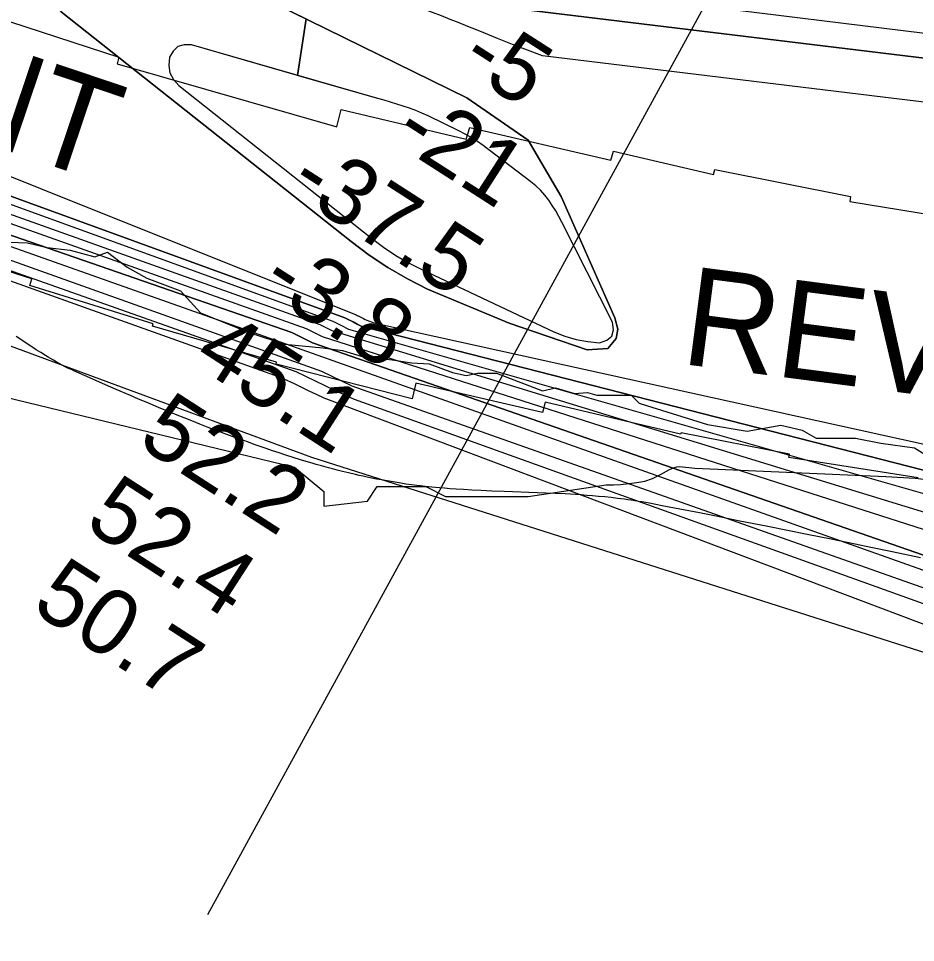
# Model space of a CAD drawing. Extents: x 3161615 to 3199515, y 867541 to 892976.
# Drawn here: x 3183730 to 3184643, y 877663 to 878603 of the extents above; entities that cross this region are included whole.
import ezdxf

# ---------------------------------------------------------------- set-up
doc = ezdxf.new("R2010")
doc.units = 0
for name, color, linetype in [('V-RIVR-EDGE', 7, 'Continuous'), ('V-RIVR-RANG', 7, 'Continuous'), ('V-ROAD-CNTR', 7, 'Continuous'), ('V-RRAP-RVMT', 7, 'Continuous'), ('V-RRAP-RVMT-IDEN', 7, 'Continuous'), ('V-SITE-VEGE', 7, 'Continuous'), ('V-TOPO-DPTH', 7, 'Continuous'), ('V-TOPO-MAJR', 7, 'Continuous'), ('V-TOPO-MINR', 7, 'Continuous'), ('V-TOPO-WATR', 7, 'Continuous')]:
    doc.layers.add(name, color=color, linetype=linetype)

msp = doc.modelspace()

# ---------------------------------------------------------------- linework, layer by layer
at = {"layer": 'V-RIVR-EDGE'}
msp.add_lwpolyline([(3183720.689197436, 878375.4628271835), (3183739.2860465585, 878374.9399670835), (3183759.3029007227, 878370.1217167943), (3183782.6625792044, 878367.2027024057), (3183807.9203144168, 878360.4639911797), (3183820.8076641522, 878365.2008788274), (3183840.798576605, 878349.8914330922), (3183860.8001015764, 878338.8738400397), (3183895.1030854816, 878325.9133818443), (3183915.5531829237, 878303.4496691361), (3183965.5752724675, 878283.2972105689), (3184001.312411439, 878271.7638324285), (3184039.929652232, 878267.8533396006), (3184059.9524022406, 878265.4194519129), (3184079.0131530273, 878259.649814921), (3184110.4773060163, 878255.7570096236), (3184130.4988768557, 878252.8462494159), (3184148.1408017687, 878251.8488751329), (3184171.962023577, 878242.7293388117), (3184185.784251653, 878239.8339077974), (3184197.2350879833, 878242.1899703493), (3184216.786861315, 878242.141624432), (3184263.47673906, 878224.3817826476), (3184276.8362446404, 878227.2100010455), (3184295.896995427, 878221.4403640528), (3184309.2517843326, 878222.3610923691), (3184318.783338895, 878219.9531463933), (3184338.335112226, 878219.904800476), (3184353.595032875, 878219.8670670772), (3184361.681819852, 878211.7401883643), (3184369.305884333, 878209.3369590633), (3184431.252145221, 878190.1087663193), (3184471.7698010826, 878183.3323216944), (3184506.119951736, 878189.4467643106), (3184527.566244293, 878184.1481039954), (3184541.852374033, 878176.0058960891), (3184581.9096657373, 878175.906845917), (3184607.648990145, 878171.0744456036), (3184641.9720199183, 878166.2208202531), (3184652.9235795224, 878159.5174840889)], dxfattribs=at)
at = {"layer": 'V-RIVR-RANG'}
msp.add_line((3183922.7562000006, 877691.4420999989), (3184460.0887000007, 878674.129099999), dxfattribs=at)
at = {"layer": 'V-ROAD-CNTR'}
for points in [[(3183762.9754372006, 878256.957458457), (3183760.3264424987, 878258.5414552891), (3183757.771447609, 878260.0984521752), (3183752.850457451, 878263.1684460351), (3183748.263466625, 878266.0984401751), (3183743.978475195, 878268.877434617), (3183727.9335072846, 878279.3824136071)], [(3184353.793255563, 878112.8857466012), (3184350.248262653, 878113.4027455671), (3184346.755269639, 878113.8867445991), (3184343.313276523, 878114.341743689), (3184339.9232833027, 878114.768742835), (3184333.2412966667, 878115.5517412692), (3184326.759309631, 878116.2417398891), (3184320.4723222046, 878116.8487386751), (3184314.3743344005, 878117.3847376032), (3184308.4613462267, 878117.8577366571), (3184302.7283576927, 878118.2777358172), (3184297.169368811, 878118.6497350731), (3184291.7803795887, 878118.980734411), (3184286.556390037, 878119.276733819), (3184276.427410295, 878119.7897327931), (3184266.9224293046, 878120.210731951), (3184258.006447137, 878120.565731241), (3184224.542514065, 878121.764728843), (3184211.993539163, 878122.246727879), (3184201.018561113, 878122.724726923), (3184191.420580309, 878123.203725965), (3184183.0285970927, 878123.6817250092), (3184175.690611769, 878124.153724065), (3184169.2756245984, 878124.6127231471), (3184163.6656358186, 878125.0527222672), (3184158.760645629, 878125.4707214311), (3184154.471654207, 878125.8627206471), (3184150.721661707, 878126.2267199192), (3184144.163674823, 878126.9147185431), (3184139.2506846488, 878127.475717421), (3184135.567692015, 878127.922716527), (3184130.049703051, 878128.6377150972), (3184124.537714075, 878129.4097135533), (3184117.716727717, 878130.4387114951), (3184111.3387404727, 878131.468709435), (3184105.3717524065, 878132.4917073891), (3184099.7897635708, 878133.4997053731), (3184094.565774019, 878134.4887033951), (3184089.6757837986, 878135.4537014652), (3184085.0987929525, 878136.3906995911), (3184080.813801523, 878137.2986977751), (3184076.8008095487, 878138.174696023), (3184073.042817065, 878139.0176943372), (3184066.007831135, 878140.6546910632), (3184059.862843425, 878142.147688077), (3184054.4928541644, 878143.499685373), (3184049.8008635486, 878144.7176829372), (3184045.6988717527, 878145.8086807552), (3184038.5278860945, 878147.7776768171), (3184033.156896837, 878149.3026737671), (3184029.1319048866, 878150.4726714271), (3184023.099916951, 878152.271667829), (3184017.073929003, 878154.1216641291), (3184009.6319438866, 878156.463659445), (3184002.443958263, 878158.7746548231), (3183995.4999721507, 878161.0506502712), (3183988.789985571, 878163.2896457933), (3183982.305998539, 878165.490641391), (3183976.038011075, 878167.651637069), (3183969.9800231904, 878169.7706328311), (3183964.1230349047, 878171.848628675), (3183958.460046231, 878173.8826246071), (3183952.984057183, 878175.8746206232), (3183942.4010783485, 878179.7866127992), (3183932.5090981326, 878183.516605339), (3183923.2611166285, 878187.0665982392), (3183914.6121339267, 878190.4375914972), (3183906.5201501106, 878193.634585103), (3183898.949165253, 878196.6615790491), (3183891.862179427, 878199.5255733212), (3183885.229192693, 878202.2325679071), (3183872.8142175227, 878207.3595576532), (3183861.9742392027, 878211.897548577), (3183852.5042581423, 878215.9055405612), (3183844.2292746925, 878219.4375334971), (3183829.7673036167, 878225.6695210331), (3183818.9353252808, 878230.3825116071), (3183802.703357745, 878237.5024973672), (3183786.4843901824, 878244.6704830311), (3183784.694393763, 878245.475481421), (3183781.1994007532, 878247.1154781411), (3183777.8494074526, 878248.7674748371), (3183774.635413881, 878250.424471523), (3183771.548420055, 878252.0774682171), (3183768.5804259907, 878253.720464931), (3183765.7254317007, 878255.3494616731), (3183762.9754372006, 878256.957458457)], [(3184648.0726670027, 878054.4238635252), (3184619.2867245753, 878060.4308515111), (3184597.6857677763, 878064.8908425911), (3184581.479800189, 878068.2108359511), (3184557.160848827, 878073.1518260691), (3184532.8298974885, 878078.047816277), (3184492.719977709, 878086.0878001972), (3184462.639037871, 878092.100788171), (3184440.074083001, 878096.5817792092), (3184423.1461168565, 878099.917772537), (3184397.7451676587, 878104.871762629), (3184385.040193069, 878107.321757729), (3184372.330218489, 878109.750752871), (3184368.513226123, 878110.4597514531), (3184364.751233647, 878111.124750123), (3184361.044241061, 878111.7497488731), (3184357.3922483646, 878112.3357477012), (3184353.793255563, 878112.8857466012)]]:
    msp.add_lwpolyline(points, dxfattribs=at)
at = {"layer": 'V-RRAP-RVMT'}
for points in [[(3183706.105000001, 878604.868999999), (3183832.337000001, 878563.8749999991), (3183830.515000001, 878556.8459999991), (3184054.028000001, 878492.8359999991), (3184058.675000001, 878510.427999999), (3184185.892000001, 878480.216999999), (3184189.658000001, 878492.086999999), (3184332.954000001, 878459.067999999), (3184335.682000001, 878467.930999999), (3184437.409000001, 878444.4469999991), (3184438.708000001, 878449.4569999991), (3184576.690000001, 878421.8749999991), (3184575.9990000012, 878416.8799999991), (3184696.595000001, 878397.3649999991)], [(3184645.811000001, 878135.6279999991), (3184514.181000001, 878156.4659999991), (3184514.756000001, 878159.6799999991), (3184404.438000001, 878181.606999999), (3184403.980000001, 878180.1739999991), (3184266.022000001, 878212.837999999), (3184263.380000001, 878202.312999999), (3184134.399000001, 878232.0349999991), (3184130.778000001, 878216.072999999), (3183992.5190000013, 878251.2309999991), (3183992.944000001, 878253.5349999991), (3183866.490000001, 878290.015999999), (3183867.1780000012, 878292.337999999), (3183741.657000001, 878331.420999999), (3183743.901000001, 878338.0819999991), (3183618.972000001, 878377.787999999)]]:
    msp.add_lwpolyline(points, dxfattribs=at)
at = {"layer": 'V-SITE-VEGE'}
for points in [[(3183704.493000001, 878220.8049999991), (3184011.230000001, 878146.5569999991), (3184040.914000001, 878121.8069999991), (3184040.914000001, 878106.9569999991), (3184085.441000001, 878111.9069999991), (3184095.335000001, 878126.756999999), (3184144.809000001, 878126.756999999), (3184164.599000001, 878116.856999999), (3184248.704000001, 878116.856999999), (3184328.175000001, 878128.685999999)], [(3184328.175000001, 878128.685999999), (3184335.568000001, 878128.5329999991), (3184342.961000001, 878129.0759999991), (3184351.210000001, 878129.8929999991), (3184359.439000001, 878130.979999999), (3184367.543000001, 878132.466999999), (3184375.383000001, 878134.983999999), (3184383.520000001, 878139.0759999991), (3184392.641000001, 878144.131999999), (3184397.630000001, 878146.3089999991), (3184400.225000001, 878146.9809999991), (3184402.8570000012, 878147.2229999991), (3184418.594000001, 878145.3709999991), (3184612.906000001, 878137.1669999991), (3184642.557000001, 878135.3159999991), (3184657.345000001, 878133.8039999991)]]:
    msp.add_lwpolyline(points, dxfattribs=at)
at = {"layer": 'V-TOPO-DPTH'}
for points in [[(3183372.849847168, 878834.8355776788), (3184249.570273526, 878611.664489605), (3185230.8329057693, 878492.6025050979), (3185239.5889615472, 878489.9185044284), (3185248.3665675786, 878487.3086996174), (3185257.1764989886, 878484.8101885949), (3185266.0079806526, 878482.3858734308), (3186088.3919671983, 878334.1032975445), (3186116.9719442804, 878329.7201433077), (3186145.491880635, 878324.9143121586)], [(3184146.4127295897, 878327.8380489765), (3184126.0131929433, 878338.3115003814), (3184106.1699994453, 878349.6822995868), (3184087.16132067, 878362.3991204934), (3184068.7089850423, 878376.0132892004), (3183773.7889948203, 878609.8285210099), (3183764.761234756, 878619.8148607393), (3183758.256994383, 878630.7938620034), (3183755.5380335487, 878643.2618555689), (3183755.3425924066, 878656.7225106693), (3183760.127324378, 878667.3596378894), (3183766.8715389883, 878675.1564646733), (3183776.5549775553, 878678.692840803), (3183788.197898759, 878679.3889164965), (3183843.7690162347, 878667.4237620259), (3183855.273961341, 878664.8631988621), (3183865.506115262, 878709.428854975)], [(3183868.6918123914, 878708.617928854), (3183865.506115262, 878709.428854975), (3183855.273961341, 878664.8631988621), (3183857.6949213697, 878664.3243852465), (3183867.0813911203, 878662.235314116), (3183890.342454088, 878656.8326768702), (3183913.5265491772, 878651.10875562), (3183936.659332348, 878645.1706450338), (3184186.6065439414, 878522.222251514), (3184248.9785296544, 878479.1657162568), (3184282.446902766, 878422.1001908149), (3184336.879298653, 878298.6185323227), (3184339.9819446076, 878286.8990336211), (3184338.405226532, 878277.5302031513), (3184329.8022996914, 878267.3921345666), (3184308.724975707, 878265.8653730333), (3184229.600789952, 878293.2191795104), (3184146.4127295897, 878327.8380489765)], [(3186145.491880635, 878324.9143121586), (3186116.9719442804, 878329.7201433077), (3186088.3919671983, 878334.1032975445), (3185266.0079806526, 878482.3858734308), (3185257.1764989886, 878484.8101885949), (3185248.3665675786, 878487.3086996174), (3185239.5889615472, 878489.9185044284), (3185230.8329057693, 878492.6025050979), (3184249.570273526, 878611.664489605), (3183868.6918123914, 878708.617928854)], [(3184146.4127295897, 878327.8380489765), (3184126.0131929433, 878338.3115003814), (3184106.1699994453, 878349.6822995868), (3184087.16132067, 878362.3991204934), (3184068.7089850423, 878376.0132892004), (3183773.7889948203, 878609.8285210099), (3183764.761234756, 878619.8148607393), (3183758.256994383, 878630.7938620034), (3183755.5380335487, 878643.2618555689), (3183755.3425924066, 878656.7225106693), (3183760.127324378, 878667.3596378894), (3183766.8715389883, 878675.1564646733), (3183776.5549775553, 878678.692840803), (3183788.197898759, 878679.3889164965), (3183843.7690162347, 878667.4237620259), (3183867.0813911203, 878662.235314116), (3183890.342454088, 878656.8326768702), (3183913.5265491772, 878651.10875562), (3183936.659332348, 878645.1706450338), (3184022.9802118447, 878602.7096253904)], [(3184022.9802118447, 878602.7096253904), (3184014.048710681, 878545.2100843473), (3183906.153296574, 878576.1449049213), (3183898.760590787, 878576.266058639), (3183892.417922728, 878574.5265625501), (3183887.6503112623, 878569.9960917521), (3183883.9327375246, 878563.6049711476), (3183883.283302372, 878555.3971410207), (3183884.3624340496, 878547.7587348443), (3183888.034415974, 878540.9744645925), (3183893.434964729, 878534.7596182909), (3184089.337076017, 878379.4456817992), (3184101.5413851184, 878370.4413060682), (3184114.1136797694, 878362.0304750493), (3184127.237952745, 878354.5099610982), (3184140.73021127, 878347.5829918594), (3184275.0582020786, 878284.4066678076), (3184286.2552080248, 878279.9537376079), (3184297.6799251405, 878276.4416430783), (3184309.446209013, 878274.3408020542), (3184321.440204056, 878273.1807967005), (3184328.944188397, 878275.7332786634), (3184334.065478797, 878279.8084991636), (3184335.612728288, 878286.1678274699), (3184334.7772838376, 878294.0498943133), (3184283.240078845, 878395.8145595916), (3184280.1536255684, 878401.5939258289), (3184276.9047591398, 878407.2756835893)], [(3184276.9047591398, 878407.2756835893), (3184273.4122729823, 878412.8110286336), (3184269.757373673, 878418.2487652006), (3184265.7590821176, 878423.3994324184), (3184261.471871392, 878428.2709921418), (3184256.751281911, 878432.7238906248), (3184251.7417732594, 878436.8976816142), (3184203.067166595, 878473.7510171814), (3184197.1702966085, 878477.9456273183), (3184191.1240657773, 878481.8960863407), (3184184.853793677, 878485.4803186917), (3184178.4341607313, 878488.8203999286), (3184146.9625092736, 878504.022327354), (3184140.800349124, 878506.8333149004), (3184134.565205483, 878509.4598021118), (3184128.220586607, 878511.8095388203), (3184121.8029842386, 878513.9747751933), (3184115.3233377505, 878515.9774659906), (3184108.834277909, 878517.9487614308), (3184102.331098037, 878519.872963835), (3184095.818504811, 878521.7657708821), (3184021.084727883, 878543.1927796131), (3184014.048710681, 878545.2100843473), (3184022.9802118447, 878602.7096253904), (3184027.690381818, 878600.3927048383)], [(3183252.667433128, 878593.1972245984), (3184062.4632930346, 878298.5288033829), (3184066.549592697, 878296.3929994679), (3184070.641684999, 878294.2684087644), (3184074.742466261, 878292.160637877), (3184078.849040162, 878290.0640802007), (3184955.5760327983, 878065.4056483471)], [(3184955.5760327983, 878065.4056483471), (3184078.849040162, 878290.0640802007), (3184074.742466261, 878292.160637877), (3184070.641684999, 878294.2684087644), (3184066.549592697, 878296.3929994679), (3184062.4632930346, 878298.5288033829), (3183252.667433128, 878593.1972245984)], [(3184027.690381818, 878600.3927048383), (3184186.6065439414, 878522.222251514), (3184248.9785296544, 878479.1657162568), (3184282.446902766, 878422.1001908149), (3184336.879298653, 878298.6185323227), (3184339.9819446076, 878286.8990336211), (3184338.405226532, 878277.5302031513), (3184329.8022996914, 878267.3921345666), (3184308.724975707, 878265.8653730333), (3184229.600789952, 878293.2191795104), (3184146.4127295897, 878327.8380489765)], [(3183212.658256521, 878585.3971045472), (3184036.985233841, 878291.612818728), (3184049.0120516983, 878285.4660348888), (3184936.3581883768, 878013.7470163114)], [(3183212.658256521, 878585.3971045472), (3184036.985233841, 878291.612818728), (3184049.0120516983, 878285.4660348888), (3184936.3581883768, 878013.7470163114)], [(3184276.9047591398, 878407.2756835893), (3184273.4122729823, 878412.8110286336), (3184269.757373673, 878418.2487652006), (3184265.7590821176, 878423.3994324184), (3184261.471871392, 878428.2709921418), (3184256.751281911, 878432.7238906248), (3184251.7417732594, 878436.8976816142), (3184203.067166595, 878473.7510171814), (3184197.1702966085, 878477.9456273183), (3184191.1240657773, 878481.8960863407), (3184184.853793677, 878485.4803186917), (3184178.4341607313, 878488.8203999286), (3184146.9625092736, 878504.022327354), (3184140.800349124, 878506.8333149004), (3184134.565205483, 878509.4598021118), (3184128.220586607, 878511.8095388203), (3184121.8029842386, 878513.9747751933), (3184115.3233377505, 878515.9774659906), (3184108.834277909, 878517.9487614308), (3184102.331098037, 878519.872963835), (3184095.818504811, 878521.7657708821), (3183906.153296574, 878576.1449049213), (3183898.760590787, 878576.266058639), (3183892.417922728, 878574.5265625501), (3183887.6503112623, 878569.9960917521), (3183883.9327375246, 878563.6049711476), (3183883.283302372, 878555.3971410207), (3183884.3624340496, 878547.7587348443), (3183888.034415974, 878540.9744645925), (3183893.434964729, 878534.7596182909), (3184089.337076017, 878379.4456817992), (3184101.5413851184, 878370.4413060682), (3184114.1136797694, 878362.0304750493), (3184127.237952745, 878354.5099610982), (3184140.73021127, 878347.5829918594), (3184275.0582020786, 878284.4066678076), (3184286.2552080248, 878279.9537376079), (3184297.6799251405, 878276.4416430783), (3184309.446209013, 878274.3408020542), (3184321.440204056, 878273.1807967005), (3184328.944188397, 878275.7332786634), (3184334.065478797, 878279.8084991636), (3184335.612728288, 878286.1678274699), (3184334.7772838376, 878294.0498943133), (3184283.240078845, 878395.8145595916), (3184280.1536255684, 878401.5939258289), (3184276.9047591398, 878407.2756835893)], [(3184953.757013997, 877951.6936236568), (3184029.256940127, 878273.0675252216), (3184008.2494205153, 878283.5851602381), (3183219.0654344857, 878556.6295615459)]]:
    msp.add_lwpolyline(points, dxfattribs=at)
at = {"layer": 'V-TOPO-MAJR'}
msp.add_lwpolyline([(3183235.315423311, 878518.6069014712), (3184012.537934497, 878243.9726394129), (3184032.2175095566, 878234.4599938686), (3184051.9365608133, 878225.0294521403), (3184071.681929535, 878215.6536462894), (3184922.869589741, 877909.9897771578)], dxfattribs=at)
at = {"layer": 'V-TOPO-MINR'}
for points in [[(3186147.2983375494, 878379.3295241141), (3186128.676513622, 878384.1360410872), (3185314.401796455, 878506.3831856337), (3184277.182839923, 878634.3805067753), (3183394.0893720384, 878877.4493847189)], [(3186145.491880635, 878324.9143121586), (3186116.9719442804, 878329.7201433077), (3186088.3919671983, 878334.1032975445), (3185266.0079806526, 878482.3858734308), (3185257.1764989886, 878484.8101885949), (3185248.3665675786, 878487.3086996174), (3185239.5889615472, 878489.9185044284), (3185230.8329057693, 878492.6025050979), (3184249.570273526, 878611.664489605), (3183372.849847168, 878834.8355776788)], [(3184248.048062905, 878570.7617867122), (3184232.838272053, 878576.6644537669), (3184217.6935068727, 878582.7389662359), (3184205.327160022, 878587.8207488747), (3184196.407203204, 878591.4655654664), (3184187.477691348, 878595.0866845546), (3184178.5338469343, 878598.6722573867), (3184169.580447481, 878602.2341327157), (3184160.6010079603, 878605.7277883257), (3184151.596411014, 878609.1542021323), (3184142.554077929, 878612.479753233), (3184133.4865874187, 878615.7380625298), (3183388.1043961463, 878797.7976993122)], [(3183773.7889948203, 878609.8285210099), (3184068.7089850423, 878376.0132892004), (3184087.16132067, 878362.3991204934), (3184106.1699994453, 878349.6822995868), (3184126.0131929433, 878338.3115003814), (3184146.4127295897, 878327.8380489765), (3184229.600789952, 878293.2191795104), (3184308.724975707, 878265.8653730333), (3184329.8022996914, 878267.3921345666), (3184338.405226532, 878277.5302031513), (3184339.9819446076, 878286.8990336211), (3184336.879298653, 878298.6185323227), (3184282.446902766, 878422.1001908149), (3184248.9785296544, 878479.1657162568), (3184186.6065439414, 878522.222251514), (3183936.659332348, 878645.1706450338)], [(3183209.3966609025, 878599.9613887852), (3184050.155685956, 878295.2155285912), (3184058.074725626, 878291.123516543), (3184066.0049089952, 878287.0533270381), (3184958.843468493, 878031.8409783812)], [(3183252.667433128, 878593.1972245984), (3184062.4632930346, 878298.5288033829), (3184066.549592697, 878296.3929994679), (3184070.641684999, 878294.2684087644), (3184074.742466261, 878292.160637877), (3184078.849040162, 878290.0640802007), (3184955.5760327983, 878065.4056483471)], [(3183199.1219689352, 878580.4398783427), (3184022.996397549, 878287.731168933), (3184039.3922816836, 878279.4390277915), (3185015.7129105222, 877966.5873512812), (3185136.9727150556, 877934.1829453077), (3185214.0046340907, 877913.3547107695), (3185290.952817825, 877892.225011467), (3185367.7753986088, 877870.6431150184), (3185444.5142440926, 877848.7597538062), (3185700.183264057, 877775.037785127), (3185717.778624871, 877769.9374630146), (3185735.364350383, 877764.8043023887), (3185752.9356229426, 877759.6218839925), (3185770.4972602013, 877754.4066270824), (3185784.5371316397, 877750.2158097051), (3185795.1173655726, 877747.2675874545), (3185805.758422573, 877744.5802286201), (3185816.490714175, 877742.2841649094), (3185827.2838288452, 877740.2489646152), (3185838.144642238, 877738.6197384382), (3185849.034609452, 877737.2691896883), (3185859.9683073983, 877736.3366570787), (3185870.931159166, 877735.6828018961), (3186703.9569149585, 877684.4115282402)], [(3184276.9047591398, 878407.2756835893), (3184273.4122729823, 878412.8110286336), (3184269.757373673, 878418.2487652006), (3184265.7590821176, 878423.3994324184), (3184261.471871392, 878428.2709921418), (3184256.751281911, 878432.7238906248), (3184251.7417732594, 878436.8976816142), (3184203.067166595, 878473.7510171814), (3184197.1702966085, 878477.9456273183), (3184191.1240657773, 878481.8960863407), (3184184.853793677, 878485.4803186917), (3184178.4341607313, 878488.8203999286), (3184146.9625092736, 878504.022327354), (3184140.800349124, 878506.8333149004), (3184134.565205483, 878509.4598021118), (3184128.220586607, 878511.8095388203), (3184121.8029842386, 878513.9747751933), (3184115.3233377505, 878515.9774659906), (3184108.834277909, 878517.9487614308), (3184102.331098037, 878519.872963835), (3184095.818504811, 878521.7657708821), (3183906.153296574, 878576.1449049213), (3183898.760590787, 878576.266058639), (3183892.417922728, 878574.5265625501), (3183887.6503112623, 878569.9960917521), (3183883.9327375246, 878563.6049711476), (3183883.283302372, 878555.3971410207), (3183884.3624340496, 878547.7587348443), (3183888.034415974, 878540.9744645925), (3183893.434964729, 878534.7596182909), (3184089.337076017, 878379.4456817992), (3184101.5413851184, 878370.4413060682), (3184114.1136797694, 878362.0304750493), (3184127.237952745, 878354.5099610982), (3184140.73021127, 878347.5829918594), (3184275.0582020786, 878284.4066678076), (3184286.2552080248, 878279.9537376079), (3184297.6799251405, 878276.4416430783), (3184309.446209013, 878274.3408020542), (3184321.440204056, 878273.1807967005), (3184328.944188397, 878275.7332786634), (3184334.065478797, 878279.8084991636), (3184335.612728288, 878286.1678274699), (3184334.7772838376, 878294.0498943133), (3184283.240078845, 878395.8145595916), (3184280.1536255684, 878401.5939258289), (3184276.9047591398, 878407.2756835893)], [(3186310.842182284, 878220.5276241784), (3186124.549740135, 878262.195887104), (3186118.406766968, 878263.575677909), (3186112.2654586, 878264.9628087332), (3186106.126647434, 878266.3609495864), (3186099.989501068, 878267.7664304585), (3186099.560733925, 878267.8650279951), (3186093.6190565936, 878269.0969319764), (3186087.650610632, 878270.1565355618), (3186081.642011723, 878270.9576885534), (3186075.6066441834, 878271.5865411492), (3185226.1748412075, 878443.570401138), (3185196.029514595, 878451.7434800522), (3184263.355392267, 878565.1168877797), (3184248.048062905, 878570.7617867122)], [(3183195.9706835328, 878557.3402740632), (3184018.6414099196, 878266.3728113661), (3184947.2009467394, 877936.616051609), (3184953.9222448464, 877934.7067343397), (3184960.654285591, 877932.8367583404), (3184967.402440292, 877931.0257942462), (3184974.1613376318, 877929.254171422), (3185024.4907818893, 877916.29716184), (3185056.4321893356, 877908.1149756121), (3185088.3865693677, 877899.9840289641), (3185120.3604082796, 877891.9299416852), (3185152.347219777, 877883.9270939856), (3185274.2835923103, 877853.5753076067), (3185367.2410861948, 877830.4060651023), (3185460.1889354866, 877807.1982468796), (3185553.12231789, 877783.93256508), (3185646.046055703, 877760.6283075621), (3185826.3588890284, 877715.3481551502), (3185832.7958533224, 877713.9068092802), (3185839.26887712, 877712.6884556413), (3185845.795990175, 877711.8045903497), (3185852.3591627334, 877711.143717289), (3186567.1772239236, 877662.85390623)], [(3183219.0654344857, 878556.6295615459), (3184008.2494205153, 878283.5851602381), (3184029.256940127, 878273.0675252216), (3184953.757013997, 877951.6936236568)], [(3183431.191191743, 878558.7478869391), (3184073.839320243, 878301.5371289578), (3184074.9397610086, 878300.9569433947), (3184075.491547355, 878300.6698453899), (3184076.0441166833, 878300.3842447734), (3184081.2853618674, 878297.688775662), (3184082.9767184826, 878296.8635210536), (3184086.4321784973, 878295.3827730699), (3184089.9785732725, 878294.1159519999), (3184091.7642444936, 878293.5148076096), (3185059.58755434, 878080.1923909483)], [(3183186.1905660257, 878548.365111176), (3184038.509437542, 878244.2763951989), (3184069.514196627, 878229.3127097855), (3184938.5595127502, 877922.4870130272), (3184953.154839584, 877918.4411928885), (3184967.7802726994, 877914.5055948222), (3184982.4257766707, 877910.6434781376), (3185094.2570193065, 877881.6035651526), (3185164.846854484, 877863.3297414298), (3185235.454895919, 877845.1267588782), (3185306.0902467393, 877827.030038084), (3185376.743803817, 877809.0041584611), (3185389.559632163, 877805.7447167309), (3185463.636664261, 877787.3679128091), (3185537.849799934, 877769.5738453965), (3185612.267090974, 877752.6538827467), (3185686.820485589, 877736.3166566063), (3185815.1843099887, 877708.977893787), (3185825.678905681, 877706.8684504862), (3185836.201471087, 877704.9204221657), (3185846.765991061, 877703.214516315), (3185857.3584807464, 877701.670025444), (3185926.158811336, 877692.4438204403)], [(3183180.481138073, 878529.3387607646), (3183995.4675630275, 878238.5669210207), (3183997.9131979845, 878237.6262189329), (3184000.3176649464, 878236.5656893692), (3184010.6292526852, 878231.562432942), (3184018.165786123, 878227.9250957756), (3184025.712354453, 878224.3088125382), (3184033.2739751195, 878220.7241101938), (3184040.8456306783, 878217.1604617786), (3184833.9494988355, 877917.8409118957)], [(3183202.7022876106, 878461.781741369), (3184028.489243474, 878156.7127221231), (3184861.0841985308, 877891.5816693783)]]:
    msp.add_lwpolyline(points, dxfattribs=at)
at = {"layer": 'V-TOPO-WATR'}
msp.add_lwpolyline([(3183212.658256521, 878585.3971045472), (3184036.985233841, 878291.612818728), (3184049.0120516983, 878285.4660348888), (3184936.3581883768, 878013.7470163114)], dxfattribs=at)

# ---------------------------------------------------------------- texts
at = {"layer": 'V-RIVR-RANG'}
for s, height, rotation, p in [('-5', 67, 327.29083333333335, (3184176.7479900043, 878553.7754752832)), ('-21', 67, 327.29083333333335, (3184108.738107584, 878478.6064856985)), ('-37.5', 67, 327.29083333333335, (3184002.109835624, 878428.2384296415)), ('-3.8', 67, 327.29083333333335, (3183973.8300953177, 878327.5538072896)), ('45.1', 66.99999999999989, 327.15832571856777, (3183905.6797590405, 878252.7954971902)), ('52.2', 66.99999999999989, 327.15832571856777, (3183849.659176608, 878169.9329721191)), ('52.4', 66.99999999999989, 327.15832571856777, (3183795.633176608, 878085.7829721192)), ('50.7', 66.99999999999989, 327.15832571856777, (3183741.6061766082, 878001.6329721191))]:
    msp.add_text(s, height=height, rotation=rotation, dxfattribs=at).set_placement(p)
at = {"layer": 'V-RRAP-RVMT-IDEN'}
for s, height, rotation, p in [('POINT', 99.99980200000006, 341.3901455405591, (3183424.522188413, 878567.5297919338)), ('REVET.', 99.99980199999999, 352.5707240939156, (3184402.677983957, 878251.9169160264))]:
    msp.add_text(s, height=height, rotation=rotation, dxfattribs=at).set_placement(p)

doc.saveas('drawing.dxf')
